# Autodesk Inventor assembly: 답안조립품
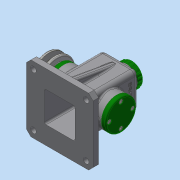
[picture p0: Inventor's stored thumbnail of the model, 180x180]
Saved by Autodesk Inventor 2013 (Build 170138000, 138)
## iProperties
Created: 2018-10
Part Number: 답안조립품
Document SubType Name: Assembly
Designer: Administrator
Author: Administrator
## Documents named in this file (14)
- C:\Users\Administrator\Desktop\481013V1013\답안조립품.iam
- C:\Users\Administrator\Desktop\481013V1013\본체.ipt
- C:\Users\Administrator\Desktop\481013V1013\V-벨트풀리.ipt
- C:\Users\Administrator\Desktop\481013V1013\뒤커버.ipt
- C:\Users\Administrator\Desktop\481013V1013\멈춤링 15 x 1.ipt
- C:\Users\Administrator\Desktop\481013V1013\베어링 15 x 35 x 11.ipt
- C:\Users\Administrator\Desktop\481013V1013\볼트 M4 x 10.ipt
- C:\Users\Administrator\Desktop\481013V1013\볼트 M6 x 12.ipt
- C:\Users\Administrator\Desktop\481013V1013\상부캡.ipt
- C:\Users\Administrator\Desktop\481013V1013\앞커버.ipt
- C:\Users\Administrator\Desktop\481013V1013\오일실 15 25 7.ipt
- C:\Users\Administrator\Desktop\481013V1013\와셔.ipt
- C:\Users\Administrator\Desktop\481013V1013\축.ipt
- C:\Users\Administrator\Desktop\481013V1013\키 5 x 5 x 14.ipt
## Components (1 placed, 1 different names)
1. V-벨트풀리:1 — 플러쉬:1
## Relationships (1: Flush 1)
- 플러쉬:1 [Flush]: V-벨트풀리:1
